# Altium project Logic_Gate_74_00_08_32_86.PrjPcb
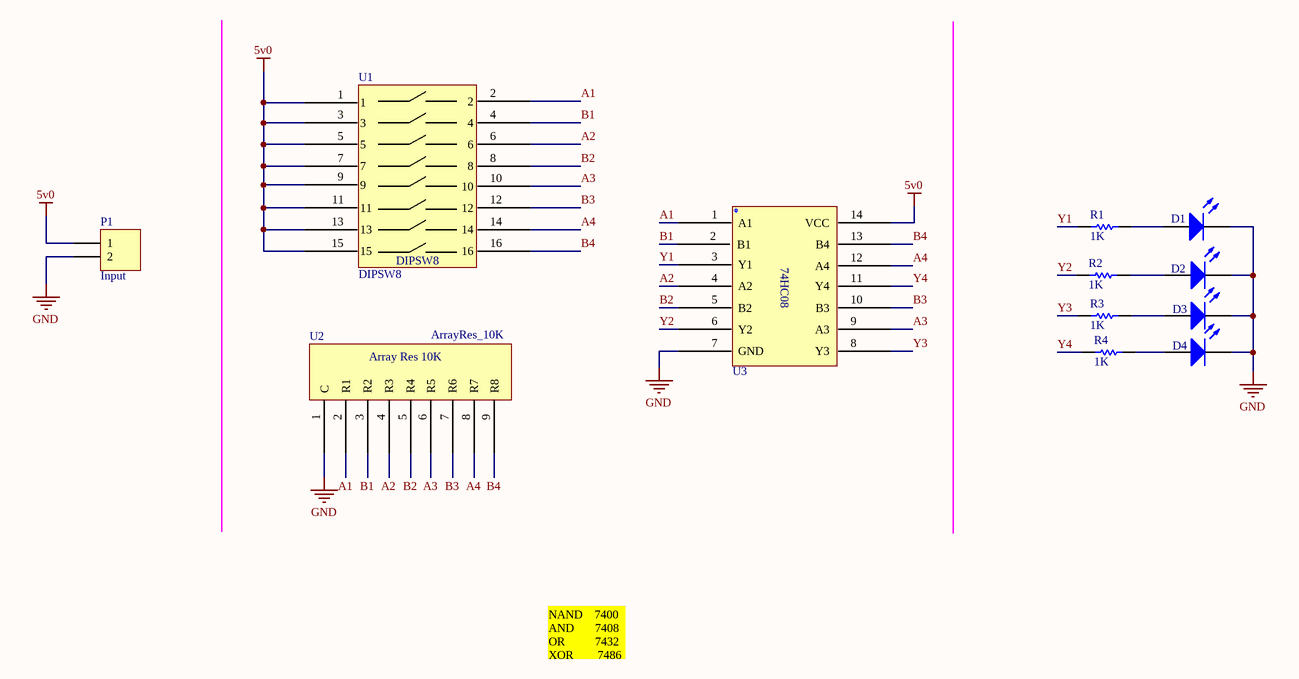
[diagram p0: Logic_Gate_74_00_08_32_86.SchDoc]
1 sheet, 12 parts. Net scope: global (net labels, ports and power ports of the same name join across sheets).
Board file: Logic_Gate_74_00_08_32_86.PcbDoc

## Sheet Logic_Gate_74_00_08_32_86.SchDoc
size A4; SheetNumber: 1; SheetTotal: 1; SPICEModelCacheCJHPFBQC: <root> / <DocumentId>CJHPFBQC</DocumentId> / <CacheFrame Number="0"> / <Model Name="led0" Kind="MDL"> / <Text>*Typ INFRARED GaAs LED: Vf=1.2V Vr=5V If=40mA trr=3uS / *LED Pinout: 1=A, 2=K / .MODEL LED0 D (IS=93.5P RS=84M N=2.63 BV=5 IBV=10U / + CJO=2.97P VJ=.75 M=.333 TT=4.32U)</Text> / </Model> / </CacheFrame> / </root>

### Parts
D1  LED0  [LED_5M]  (value not drawn)
D2  LED0  [LED_5M]  (value not drawn)
D3  LED0  [LED_5M]  (value not drawn)
D4  LED0  [LED_5M]  (value not drawn)
P1  Input  [K300_5_2]
R1  value 1K  [Resistor]  (hidden comment: Res1)
R2  value 1K  [Resistor]  (hidden comment: Res1)
R3  value 1K  [Resistor]  (hidden comment: Res1)
R4  value 1K  [Resistor]  (hidden comment: Res1)
U1  DIPSW8  [DIPSW8]
U2  ArrayRes_10K  [ArrayRes_10K]
U3  74HC08  [74HC08]  (value not drawn)

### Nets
5v0: P1.1 U1.1 U1.3 U1.5 U1.7 U1.9 U1.11 U1.13 U1.15 U3.14(VCC)
GND: D1.2(K) D2.2(K) D3.2(K) D4.2(K) P1.2 U2.1(C) U3.7(GND)
A1: U1.2 U2.2(R1) U3.1(A1)
A2: U1.6 U2.4(R3) U3.4(A2)
A3: U1.10 U2.6(R5) U3.9(A3)
A4: U1.14 U2.8(R7) U3.12(A4)
B1: U1.4 U2.3(R2) U3.2(B1)
B2: U1.8 U2.5(R4) U3.5(B2)
B3: U1.12 U2.7(R6) U3.10(B3)
B4: U1.16 U2.9(R8) U3.13(B4)
Y1: R1.1 U3.3(Y1)
Y2: R2.1 U3.6(Y2)
Y3: R3.1 U3.8(Y3)
Y4: R4.1 U3.11(Y4)
NetD1_1: D1.1(A) R1.2
NetD2_1: D2.1(A) R2.2
NetD3_1: D3.1(A) R3.2
NetD4_1: D4.1(A) R4.2

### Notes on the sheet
- NAND    7400
  AND       7408
  OR          7432
  XOR        7486

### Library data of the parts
D1-D4 = LED0: Typical INFRARED GaAs LED
P1 = Header 2: Header, 2-Pin
R1-R4 = Res1: Resistor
